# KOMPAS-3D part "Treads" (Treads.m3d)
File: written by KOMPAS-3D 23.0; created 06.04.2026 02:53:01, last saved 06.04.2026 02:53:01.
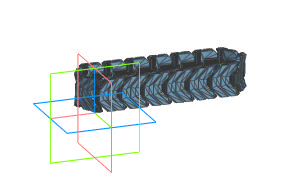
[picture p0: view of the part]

Document properties: Автор: Стас; Полное имя файла: C:\Users\Стас\Desktop\Tank Tread - 332816\files\Treads.m3d

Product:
- Part/product: Treads

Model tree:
1. Полигональный объект:1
